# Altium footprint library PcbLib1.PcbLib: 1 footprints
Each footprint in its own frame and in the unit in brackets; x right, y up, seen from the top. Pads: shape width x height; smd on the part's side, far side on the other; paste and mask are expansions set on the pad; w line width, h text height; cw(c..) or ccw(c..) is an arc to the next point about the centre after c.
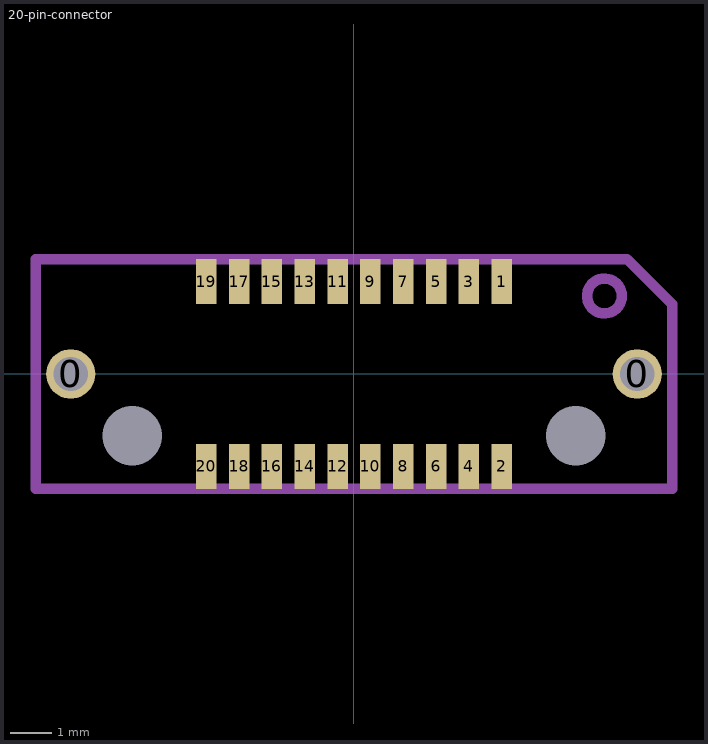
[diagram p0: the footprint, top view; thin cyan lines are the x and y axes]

## 20-pin-connector [mm] "ERF8-010-05.0-L-DV-L-TR"
pads (24):
  round 1.2 hole 0.83: 0(-6.9,0) 0(6.9,0)
  round 0 hole 1.45 unplated: 0(-5.4,-1.5) 0(5.4,-1.5)
  rect 0.5x1.1 smd: 1(3.6,2.25) 2(3.6,-2.25) 3(2.8,2.25) 4(2.8,-2.25) 5(2,2.25) 6(2,-2.25) 7(1.2,2.25) 8(1.2,-2.25) 9(0.4,2.25) 10(0.4,-2.25) 11(-0.4,2.25) 12(-0.4,-2.25) 13(-1.2,2.25) 14(-1.2,-2.25) 15(-2,2.25) 16(-2,-2.25) 17(-2.8,2.25) 18(-2.8,-2.25) 19(-3.6,2.25) 20(-3.6,-2.25)
Mechanical 13:
  circle w0.254: c6.1,1.9 r0.424
  lines w0.254: -7.75,-2.8 -7.75,2.8 6.65,2.8 7.75,1.7 7.75,-2.8 -7.75,-2.8
3D body: height 5.11, standoff -1.26, extent -7.75,-2.8 7.75,2.8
